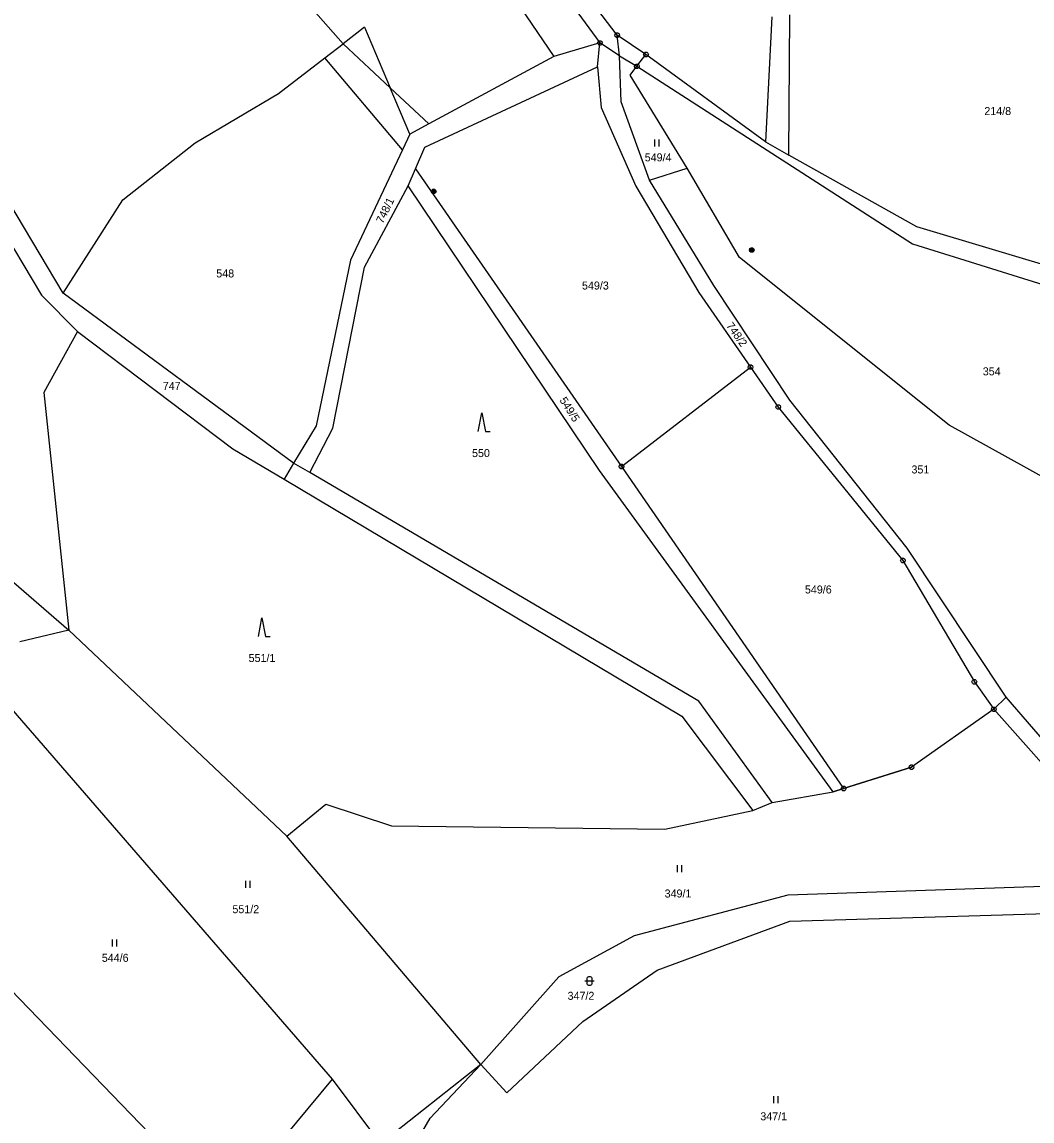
# Model space of a CAD drawing. Extents: x -694465 to -690527, y -983694 to -978978.
# Drawn here: x -692743.9 to -692529.4, y -981430.2 to -981196.7 of the extents above; entities that cross this region are included whole.
import ezdxf

# ---------------------------------------------------------------- set-up
doc = ezdxf.new("R2010")
doc.units = 0
for name, color, linetype in [('Vrstva 1', 7, 'Continuous'), ('Vrstva 18', 7, 'Continuous'), ('Vrstva 24', 7, 'Continuous'), ('Vrstva 25', 7, 'Continuous'), ('Vrstva 26', 7, 'Continuous')]:
    doc.layers.add(name, color=color, linetype=linetype)

msp = doc.modelspace()

# ---------------------------------------------------------------- linework, layer by layer
at = {"layer": 'Vrstva 1'}
for points in [[(-692722.97, -981147.7), (-692675.72, -981201.4)], [(-692617.5, -981199.52), (-692641.63, -981167.82)], [(-692644.17, -981169.72), (-692621.15, -981201.18)], [(-692652.97, -981171.66), (-692630.98, -981204.09)], [(-692584.64, -981195.61), (-692585.98, -981222.21)], [(-692581.05, -981225.05), (-692580.85, -981195.24)], [(-692671.13, -981197.86), (-692675.72, -981201.4)], [(-692671.13, -981197.86), (-692665.68, -981210.75)], [(-692621.15, -981201.18), (-692630.98, -981204.09)], [(-692621.67, -981206.28), (-692621.15, -981201.18)], [(-692617, -981203.9), (-692621.15, -981201.18)], [(-692611.37, -981203.65), (-692617.5, -981199.52)], [(-692617, -981203.9), (-692617.5, -981199.52)], [(-692679.551, -981204.357), (-692675.72, -981201.4)], [(-692675.72, -981201.4), (-692665.68, -981210.75)], [(-692689.39, -981211.95), (-692679.551, -981204.357)], [(-692663.083, -981223.893), (-692679.551, -981204.357)], [(-692630.98, -981204.09), (-692657.48, -981218.4)], [(-692616.66, -981213.69), (-692617, -981203.9)], [(-692617, -981203.9), (-692613.32, -981206.15)], [(-692613.32, -981206.15), (-692611.37, -981203.65)], [(-692585.98, -981222.21), (-692611.37, -981203.65)], [(-692658.35, -981223.3), (-692621.67, -981206.28)], [(-692621.67, -981206.28), (-692620.92, -981214.91)], [(-692614.74, -981208.05), (-692613.32, -981206.15)], [(-692602.59, -981227.76), (-692614.74, -981208.05)], [(-692613.32, -981206.15), (-692554.8, -981243.83)], [(-692707.15, -981222.38), (-692689.39, -981211.95)], [(-692665.68, -981210.75), (-692657.48, -981218.4)], [(-692661.53, -981220.59), (-692665.68, -981210.75)], [(-692620.92, -981214.91), (-692613.53, -981231.63)], [(-692610.63, -981230.31), (-692616.66, -981213.69)], [(-692657.48, -981218.4), (-692661.53, -981220.59)], [(-692661.53, -981220.59), (-692663.083, -981223.893)], [(-692585.98, -981222.21), (-692581.05, -981225.05)], [(-692722.46, -981234.52), (-692707.15, -981222.38)], [(-692663.083, -981223.893), (-692674.11, -981247.34)], [(-692660.35, -981227.94), (-692658.35, -981223.3)], [(-692553.81, -981240.22), (-692581.05, -981225.05)], [(-692661.91, -981231.54), (-692660.35, -981227.94)], [(-692660.35, -981227.94), (-692616.57, -981291.15)], [(-692610.63, -981230.31), (-692602.59, -981227.76)], [(-692591.52, -981246.76), (-692602.59, -981227.76)], [(-692671.17, -981248.84), (-692661.91, -981231.54)], [(-692621.22, -981292), (-692661.91, -981231.54)], [(-692613.53, -981231.63), (-692600.15, -981254.22)], [(-692596.99, -981252.69), (-692610.63, -981230.31)], [(-692735.17, -981254.35), (-692748.28, -981232.31)], [(-692735.17, -981254.35), (-692722.46, -981234.52)], [(-692749.5, -981238.45), (-692739.74, -981254.77)], [(-692520.98, -981250.09), (-692553.81, -981240.22)], [(-692554.8, -981243.83), (-692522.31, -981254.01)], [(-692674.11, -981247.34), (-692681.4, -981282.52)], [(-692546.95, -981282.33), (-692591.52, -981246.76)], [(-692677.89, -981282.97), (-692671.17, -981248.84)], [(-692739.74, -981254.77), (-692732.09, -981262.48)], [(-692686.25, -981290.45), (-692735.17, -981254.35)], [(-692600.15, -981254.22), (-692589.16, -981270.03)], [(-692580.84, -981277.08), (-692596.99, -981252.69)], [(-692732.09, -981262.48), (-692739.25, -981275.42)], [(-692732.09, -981262.48), (-692699.09, -981287.38)], [(-692616.57, -981291.15), (-692589.16, -981270.03)], [(-692589.16, -981270.03), (-692583.27, -981278.51)], [(-692739.25, -981275.42), (-692733.93, -981325.91)], [(-692555.89, -981308.52), (-692580.84, -981277.08)], [(-692788.77, -981278.44), (-692733.93, -981325.91)], [(-692583.27, -981278.51), (-692556.8, -981311.1)], [(-692681.4, -981282.52), (-692686.25, -981290.45)], [(-692682.75, -981292.42), (-692677.89, -981282.97)], [(-692513.38, -981300.97), (-692546.95, -981282.33)], [(-692699.09, -981287.38), (-692688.228, -981293.848)], [(-692686.25, -981290.45), (-692688.228, -981293.848)], [(-692682.75, -981292.42), (-692686.25, -981290.45)], [(-692571.63, -981360.22), (-692621.22, -981292)], [(-692616.57, -981291.15), (-692569.391, -981359.518)], [(-692688.228, -981293.848), (-692603.77, -981344.14)], [(-692600.17, -981340.95), (-692682.75, -981292.42)], [(-692534.89, -981340.16), (-692555.89, -981308.52)], [(-692556.8, -981311.1), (-692541.63, -981336.87)], [(-692733.93, -981325.91), (-692744.38, -981328.39)], [(-692733.93, -981325.91), (-692687.69, -981369.65)], [(-692541.63, -981336.87), (-692537.48, -981342.7)], [(-692749.1, -981339.29), (-692678.06, -981421.25)], [(-692584.55, -981362.51), (-692600.17, -981340.95)], [(-692537.48, -981342.7), (-692534.89, -981340.16)], [(-692517.25, -981360.5), (-692534.89, -981340.16)], [(-692537.48, -981342.7), (-692554.97, -981355)], [(-692537.48, -981342.7), (-692520.03, -981362.38)], [(-692603.77, -981344.14), (-692588.68, -981364.22)], [(-692569.391, -981359.518), (-692554.97, -981355)], [(-692554.97, -981355), (-692569.39, -981359.52)], [(-692571.63, -981360.22), (-692569.391, -981359.518)], [(-692569.39, -981359.52), (-692571.63, -981360.22)], [(-692569.391, -981359.518), (-692569.39, -981359.52)], [(-692584.55, -981362.51), (-692571.63, -981360.22)], [(-692687.69, -981369.65), (-692679.34, -981362.89)], [(-692679.34, -981362.89), (-692665.45, -981367.48)], [(-692607.34, -981368.18), (-692588.68, -981364.22)], [(-692588.68, -981364.22), (-692584.55, -981362.51)], [(-692665.45, -981367.48), (-692607.34, -981368.18)], [(-692646.42, -981418.18), (-692687.69, -981369.65)], [(-692512.29, -981379.85), (-692581.22, -981382.15)], [(-692581.22, -981382.15), (-692613.85, -981390.8)], [(-692580.81, -981387.7), (-692509.49, -981385.58)], [(-692609, -981398.12), (-692580.81, -981387.7)], [(-692701.11, -981449.08), (-692758.21, -981389.98)], [(-692613.85, -981390.8), (-692629.88, -981399.51)], [(-692629.88, -981399.51), (-692646.42, -981418.18)], [(-692624.78, -981409.02), (-692609, -981398.12)], [(-692640.9, -981424.2), (-692624.78, -981409.02)], [(-692646.42, -981418.18), (-692667.78, -981435)], [(-692657.22, -981429.56), (-692646.42, -981418.18)], [(-692646.42, -981418.18), (-692640.9, -981424.2)], [(-692678.06, -981421.25), (-692701.11, -981449.08)], [(-692678.06, -981421.25), (-692667.78, -981435)], [(-692667.38, -981447.14), (-692657.22, -981429.56)]]:
    msp.add_lwpolyline(points, dxfattribs=at)
at = {"layer": 'Vrstva 24'}
for points in [[(-692620.996, -981200.704), (-692620.746, -981200.886), (-692620.65, -981201.18), (-692620.746, -981201.474), (-692620.996, -981201.656), (-692621.304, -981201.656), (-692621.554, -981201.474), (-692621.65, -981201.18), (-692621.554, -981200.886), (-692621.304, -981200.704)], [(-692617.346, -981199.044), (-692617.096, -981199.226), (-692617, -981199.52), (-692617.096, -981199.814), (-692617.346, -981199.996), (-692617.654, -981199.996), (-692617.904, -981199.814), (-692618, -981199.52), (-692617.904, -981199.226), (-692617.654, -981199.044)], [(-692611.216, -981203.174), (-692610.966, -981203.356), (-692610.87, -981203.65), (-692610.966, -981203.944), (-692611.216, -981204.126), (-692611.524, -981204.126), (-692611.774, -981203.944), (-692611.87, -981203.65), (-692611.774, -981203.356), (-692611.524, -981203.174)], [(-692611.216, -981203.174), (-692610.966, -981203.356), (-692610.87, -981203.65), (-692610.966, -981203.944), (-692611.216, -981204.126), (-692611.524, -981204.126), (-692611.774, -981203.944), (-692611.87, -981203.65), (-692611.774, -981203.356), (-692611.524, -981203.174)], [(-692613.166, -981205.674), (-692612.916, -981205.856), (-692612.82, -981206.15), (-692612.916, -981206.444), (-692613.166, -981206.626), (-692613.474, -981206.626), (-692613.724, -981206.444), (-692613.82, -981206.15), (-692613.724, -981205.856), (-692613.474, -981205.674)], [(-692613.166, -981205.674), (-692612.916, -981205.856), (-692612.82, -981206.15), (-692612.916, -981206.444), (-692613.166, -981206.626), (-692613.474, -981206.626), (-692613.724, -981206.444), (-692613.82, -981206.15), (-692613.724, -981205.856), (-692613.474, -981205.674)], [(-692589.006, -981269.554), (-692588.756, -981269.736), (-692588.66, -981270.03), (-692588.756, -981270.324), (-692589.006, -981270.506), (-692589.314, -981270.506), (-692589.564, -981270.324), (-692589.66, -981270.03), (-692589.564, -981269.736), (-692589.314, -981269.554)], [(-692583.116, -981278.034), (-692582.866, -981278.216), (-692582.77, -981278.51), (-692582.866, -981278.804), (-692583.116, -981278.986), (-692583.424, -981278.986), (-692583.674, -981278.804), (-692583.77, -981278.51), (-692583.674, -981278.216), (-692583.424, -981278.034)], [(-692616.416, -981290.674), (-692616.166, -981290.856), (-692616.07, -981291.15), (-692616.166, -981291.444), (-692616.416, -981291.626), (-692616.724, -981291.626), (-692616.974, -981291.444), (-692617.07, -981291.15), (-692616.974, -981290.856), (-692616.724, -981290.674)], [(-692556.646, -981310.624), (-692556.396, -981310.806), (-692556.3, -981311.1), (-692556.396, -981311.394), (-692556.646, -981311.576), (-692556.954, -981311.576), (-692557.204, -981311.394), (-692557.3, -981311.1), (-692557.204, -981310.806), (-692556.954, -981310.624)], [(-692541.476, -981336.394), (-692541.226, -981336.576), (-692541.13, -981336.87), (-692541.226, -981337.164), (-692541.476, -981337.346), (-692541.784, -981337.346), (-692542.034, -981337.164), (-692542.13, -981336.87), (-692542.034, -981336.576), (-692541.784, -981336.394)], [(-692537.326, -981342.224), (-692537.076, -981342.406), (-692536.98, -981342.7), (-692537.076, -981342.994), (-692537.326, -981343.176), (-692537.634, -981343.176), (-692537.884, -981342.994), (-692537.98, -981342.7), (-692537.884, -981342.406), (-692537.634, -981342.224)], [(-692537.326, -981342.224), (-692537.076, -981342.406), (-692536.98, -981342.7), (-692537.076, -981342.994), (-692537.326, -981343.176), (-692537.634, -981343.176), (-692537.884, -981342.994), (-692537.98, -981342.7), (-692537.884, -981342.406), (-692537.634, -981342.224)], [(-692554.816, -981354.524), (-692554.566, -981354.706), (-692554.47, -981355), (-692554.566, -981355.294), (-692554.816, -981355.476), (-692555.124, -981355.476), (-692555.374, -981355.294), (-692555.47, -981355), (-692555.374, -981354.706), (-692555.124, -981354.524)], [(-692554.816, -981354.524), (-692554.566, -981354.706), (-692554.47, -981355), (-692554.566, -981355.294), (-692554.816, -981355.476), (-692555.124, -981355.476), (-692555.374, -981355.294), (-692555.47, -981355), (-692555.374, -981354.706), (-692555.124, -981354.524)], [(-692569.236, -981359.044), (-692568.986, -981359.226), (-692568.89, -981359.52), (-692568.986, -981359.814), (-692569.236, -981359.996), (-692569.544, -981359.996), (-692569.794, -981359.814), (-692569.89, -981359.52), (-692569.794, -981359.226), (-692569.544, -981359.044)], [(-692569.236, -981359.044), (-692568.986, -981359.226), (-692568.89, -981359.52), (-692568.986, -981359.814), (-692569.236, -981359.996), (-692569.544, -981359.996), (-692569.794, -981359.814), (-692569.89, -981359.52), (-692569.794, -981359.226), (-692569.544, -981359.044)]]:
    msp.add_lwpolyline(points, close=True, dxfattribs=at)
for points in [[(-692621.269, -981201.18), (-692621.03, -981201.18)], [(-692617.619, -981199.52), (-692617.38, -981199.52)], [(-692611.489, -981203.65), (-692611.25, -981203.65)], [(-692611.489, -981203.65), (-692611.25, -981203.65)], [(-692613.439, -981206.15), (-692613.2, -981206.15)], [(-692613.439, -981206.15), (-692613.2, -981206.15)], [(-692589.279, -981270.03), (-692589.04, -981270.03)], [(-692583.389, -981278.51), (-692583.15, -981278.51)], [(-692616.689, -981291.15), (-692616.45, -981291.15)], [(-692556.919, -981311.1), (-692556.68, -981311.1)], [(-692541.749, -981336.87), (-692541.51, -981336.87)], [(-692537.599, -981342.7), (-692537.36, -981342.7)], [(-692537.599, -981342.7), (-692537.36, -981342.7)], [(-692555.089, -981355), (-692554.85, -981355)], [(-692555.089, -981355), (-692554.85, -981355)], [(-692569.509, -981359.52), (-692569.27, -981359.52)], [(-692569.509, -981359.52), (-692569.27, -981359.52)]]:
    msp.add_lwpolyline(points, dxfattribs=at)
at = {"layer": 'Vrstva 25'}
for points in [[(-692609.58, -981221.67), (-692609.58, -981223.17)], [(-692608.58, -981223.17), (-692608.58, -981221.67)], [(-692646.99, -981283.74), (-692646.24, -981279.74), (-692645.49, -981283.74), (-692644.49, -981283.74)], [(-692693.69, -981327.26), (-692692.94, -981323.26), (-692692.19, -981327.26), (-692691.19, -981327.26)], [(-692604.74, -981375.78), (-692604.74, -981377.28)], [(-692603.74, -981377.28), (-692603.74, -981375.78)], [(-692696.46, -981379.11), (-692696.46, -981380.61)], [(-692695.46, -981380.61), (-692695.46, -981379.11)], [(-692724.73, -981391.58), (-692724.73, -981393.08)], [(-692723.73, -981393.08), (-692723.73, -981391.58)], [(-692624.38, -981400.41), (-692622.38, -981400.41)], [(-692584.32, -981424.87), (-692584.32, -981426.37)], [(-692583.32, -981426.37), (-692583.32, -981424.87)]]:
    msp.add_lwpolyline(points, dxfattribs=at)
msp.add_lwpolyline([(-692623.88, -981399.91), (-692623.785, -981399.616), (-692623.535, -981399.434), (-692623.225, -981399.434), (-692622.975, -981399.616), (-692622.88, -981399.91), (-692622.88, -981400.91), (-692622.975, -981401.204), (-692623.225, -981401.386), (-692623.535, -981401.386), (-692623.785, -981401.204), (-692623.88, -981400.91)], close=True, dxfattribs=at)
at = {"layer": 'Vrstva 26'}
for points in [[(-692656.625, -981232.244), (-692656.315, -981232.244), (-692656.065, -981232.426), (-692655.97, -981232.72), (-692656.065, -981233.014), (-692656.315, -981233.196), (-692656.625, -981233.196), (-692656.875, -981233.014), (-692656.97, -981232.72), (-692656.875, -981232.426), (-692656.625, -981232.244), (-692656.59, -981232.28), (-692656.35, -981232.28), (-692656.19, -981232.36), (-692656.75, -981232.36), (-692656.83, -981232.44), (-692656.11, -981232.44), (-692656.11, -981232.52), (-692656.83, -981232.52), (-692656.872, -981232.6), (-692656.07, -981232.601), (-692656.03, -981232.68), (-692656.91, -981232.68), (-692656.91, -981232.76), (-692656.03, -981232.76), (-692656.061, -981232.839), (-692656.875, -981232.839), (-692656.869, -981232.92), (-692656.061, -981232.92), (-692656.11, -981233), (-692656.83, -981233), (-692656.75, -981233.08), (-692656.19, -981233.08), (-692656.298, -981233.159), (-692656.638, -981233.159)], [(-692656.625, -981232.244), (-692656.315, -981232.244), (-692656.065, -981232.426), (-692655.97, -981232.72), (-692656.065, -981233.014), (-692656.315, -981233.196), (-692656.625, -981233.196), (-692656.875, -981233.014), (-692656.97, -981232.72), (-692656.875, -981232.426), (-692656.625, -981232.244), (-692656.59, -981232.28), (-692656.35, -981232.28), (-692656.19, -981232.36), (-692656.75, -981232.36), (-692656.83, -981232.44), (-692656.11, -981232.44), (-692656.11, -981232.52), (-692656.83, -981232.52), (-692656.872, -981232.6), (-692656.07, -981232.601), (-692656.03, -981232.68), (-692656.91, -981232.68), (-692656.91, -981232.76), (-692656.03, -981232.76), (-692656.061, -981232.839), (-692656.875, -981232.839), (-692656.869, -981232.92), (-692656.061, -981232.92), (-692656.11, -981233), (-692656.83, -981233), (-692656.75, -981233.08), (-692656.19, -981233.08), (-692656.298, -981233.159), (-692656.638, -981233.159)], [(-692589.065, -981244.694), (-692588.755, -981244.694), (-692588.505, -981244.876), (-692588.41, -981245.17), (-692588.505, -981245.464), (-692588.755, -981245.646), (-692589.065, -981245.646), (-692589.315, -981245.464), (-692589.41, -981245.17), (-692589.315, -981244.876), (-692589.065, -981244.694), (-692589.03, -981244.73), (-692588.79, -981244.73), (-692588.63, -981244.81), (-692589.19, -981244.81), (-692589.27, -981244.89), (-692588.55, -981244.89), (-692588.55, -981244.97), (-692589.27, -981244.97), (-692589.312, -981245.05), (-692588.51, -981245.051), (-692588.47, -981245.13), (-692589.35, -981245.13), (-692589.35, -981245.21), (-692588.47, -981245.21), (-692588.501, -981245.289), (-692589.315, -981245.289), (-692589.309, -981245.37), (-692588.501, -981245.37), (-692588.55, -981245.45), (-692589.27, -981245.45), (-692589.19, -981245.53), (-692588.63, -981245.53), (-692588.738, -981245.609), (-692589.078, -981245.609)]]:
    msp.add_lwpolyline(points, dxfattribs=at)

# ---------------------------------------------------------------- texts
at = {"layer": 'Vrstva 18'}
for s, p in [('214/8', (-692539.509, -981216.5)), ('549/4', (-692611.64, -981226.34)), ('548', (-692702.641, -981250.99)), ('549/3', (-692624.963, -981253.56)), ('354', (-692539.838, -981271.78)), ('747', (-692713.994, -981274.87)), ('550', (-692648.315, -981289.14)), ('351', (-692554.983, -981292.62)), ('549/6', (-692577.613, -981318.11)), ('551/1', (-692695.771, -981332.66)), ('349/1', (-692607.412, -981382.68)), ('551/2', (-692699.213, -981386.01)), ('544/6', (-692726.953, -981396.34)), ('347/2', (-692628.024, -981404.41)), ('347/1', (-692587.092, -981430))]:
    msp.add_text(s, height=1.7, dxfattribs=at).set_placement(p)
for s, rotation, p in [('748/1', 63.88479, (-692667.272, -981239.678)), ('748/2', 305.10003, (-692594.399, -981261.252)), ('549/5', 302.40713, (-692629.81, -981277.062))]:
    msp.add_text(s, height=1.7, rotation=rotation, dxfattribs=at).set_placement(p)

doc.saveas('drawing.dxf')
